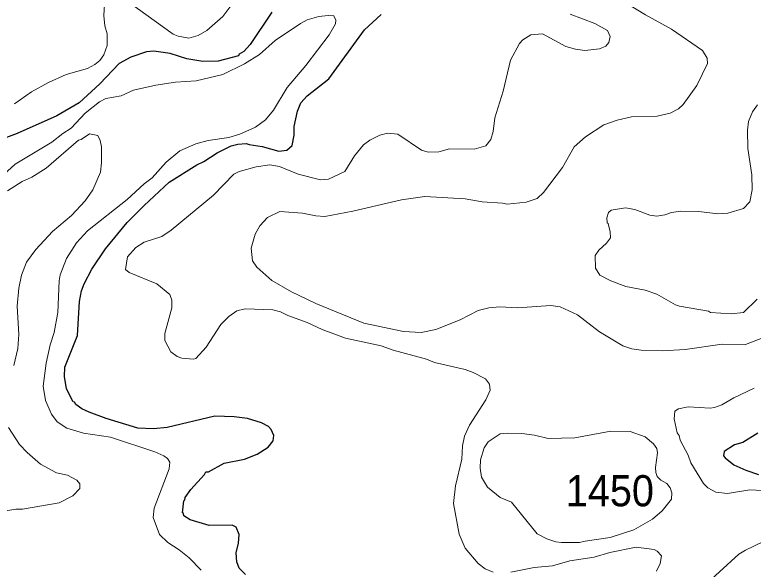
# Model space of a CAD drawing. Extents: x 598.3 to 623.2, y 6902.2 to 6930.1.
# Drawn here: x 611.225 to 613.12, y 6907.601 to 6909.024 of the extents above; entities that cross this region are included whole.
import ezdxf

# ---------------------------------------------------------------- set-up
doc = ezdxf.new("R2010")
doc.units = 0
doc.header["$LTSCALE"] = 0.032
doc.layers.add('1', color=7, linetype='Continuous', lineweight=25)
doc.layers.add('2', color=7, linetype='Continuous', lineweight=13)
doc.layers.add('21', color=7, linetype='Continuous')

msp = doc.modelspace()

# ---------------------------------------------------------------- linework, layer by layer
at = {"layer": '1'}
for points in [[(611.7929, 6907.7085), (611.783, 6907.7136), (611.7235, 6907.7128), (611.6749, 6907.7272), (611.6588, 6907.7377), (611.6577, 6907.7439), (611.6553, 6907.7456), (611.6585, 6907.7765), (611.6616, 6907.7787), (611.6621, 6907.7846), (611.6767, 6907.8057), (611.7115, 6907.8436), (611.7152, 6907.851), (611.722, 6907.8507), (611.7623, 6907.8732), (611.8141, 6907.8837), (611.8473, 6907.8957), (611.8748, 6907.914), (611.888, 6907.9301), (611.8898, 6907.9439), (611.8828, 6907.9594), (611.876, 6907.9671), (611.8584, 6907.9769), (611.8219, 6907.988), (611.7882, 6907.9921), (611.7382, 6907.9938), (611.616, 6907.9645), (611.5814, 6907.9614), (611.5412, 6907.963), (611.4597, 6907.9877), (611.4156, 6908.0036), (611.3975, 6908.0125), (611.3821, 6908.024), (611.3783, 6908.03), (611.3748, 6908.0307), (611.3581, 6908.0636), (611.3525, 6908.0954), (611.3538, 6908.1191), (611.3864, 6908.201), (611.3913, 6908.2883), (611.3964, 6908.3156), (611.4028, 6908.3336), (611.4231, 6908.3712), (611.4582, 6908.4233), (611.5138, 6908.491), (611.557, 6908.5349), (611.6214, 6908.5945), (611.6922, 6908.6387), (611.7105, 6908.6471), (611.744, 6908.6695), (611.7804, 6908.6873), (611.7977, 6908.6923), (611.819, 6908.6938), (611.8263, 6908.6908), (611.8601, 6908.686), (611.9022, 6908.6738), (611.9229, 6908.6766), (611.9369, 6908.6886), (611.9417, 6908.7155), (611.9418, 6908.7371), (611.9504, 6908.7766), (611.9594, 6908.798), (611.9755, 6908.8159), (612.0304, 6908.8596), (612.122, 6908.9851), (612.1649, 6909.0246)], [(611.8846, 6909.0308), (611.8294, 6908.9476), (611.8128, 6908.9301), (611.801, 6908.923), (611.7987, 6908.9187), (611.7472, 6908.9052), (611.7073, 6908.9043), (611.6668, 6908.9108), (611.6241, 6908.9247), (611.582, 6908.9311), (611.5629, 6908.9294), (611.5232, 6908.9152), (611.4931, 6908.8993)], [(611.4931, 6908.8993), (611.4437, 6908.8467), (611.39, 6908.7979), (611.3328, 6908.765), (611.2317, 6908.7193), (611.1319, 6908.6824)], [(613.1315, 6907.9499), (613.0931, 6907.9259), (613.0718, 6907.92), (613.0447, 6907.9033), (613.0435, 6907.892), (613.0471, 6907.8868), (613.0698, 6907.8688), (613.1002, 6907.8551), (613.1333, 6907.844)], [(611.8172, 6907.5874), (611.8011, 6907.6034), (611.7952, 6907.62), (611.7929, 6907.6424), (611.7992, 6907.668), (611.801, 6907.6903), (611.7929, 6907.7085)]]:
    msp.add_lwpolyline(points, dxfattribs=at)
at = {"layer": '2'}
for points in [[(611.7846, 6909.0539), (611.7591, 6909.0197), (611.7181, 6908.9836), (611.6952, 6908.9713), (611.672, 6908.9643), (611.6444, 6908.969), (611.6313, 6908.9746), (611.519, 6909.0558)], [(612.2168, 6908.549), (612.2774, 6908.5579), (612.3808, 6908.5514), (612.4241, 6908.5443), (612.476, 6908.5409), (612.4887, 6908.5378), (612.5366, 6908.5433), (612.5649, 6908.5523), (612.5819, 6908.5676), (612.63, 6908.6319), (612.6603, 6908.6855), (612.6892, 6908.7111), (612.7365, 6908.7415), (612.7701, 6908.7537), (612.8076, 6908.7619), (612.8727, 6908.7637), (612.9067, 6908.7716), (612.9275, 6908.7828), (612.9398, 6908.7942), (612.9748, 6908.8423), (613.0021, 6908.899), (613.0017, 6908.9128), (612.989, 6908.9328), (612.9102, 6908.9876), (612.8433, 6909.0238), (612.7912, 6909.0553)], [(611.4556, 6909.0503), (611.4537, 6909.0225), (611.4565, 6908.9957), (611.4625, 6908.9749), (611.4625, 6908.9457), (611.4534, 6908.9209), (611.4431, 6908.9068), (611.4302, 6908.8965), (611.4116, 6908.8861), (611.3567, 6908.8707), (611.3119, 6908.8501), (611.268, 6908.8265), (611.2248, 6908.7952)], [(612.0438, 6909.0215), (612.029, 6909.0225), (612.0049, 6909.0193), (611.9755, 6909.0111), (611.9577, 6909.0014), (611.8932, 6908.9578), (611.8527, 6908.9224), (611.8147, 6908.8984), (611.7591, 6908.8704), (611.6908, 6908.8547), (611.6377, 6908.851), (611.5867, 6908.8435), (611.5296, 6908.8305), (611.4984, 6908.8162), (611.4585, 6908.8088), (611.4421, 6908.8006), (611.406, 6908.7717), (611.37, 6908.7334), (611.3481, 6908.7194), (611.3199, 6908.697), (611.2258, 6908.6408), (611.1683, 6908.5883)], [(611.7036, 6907.5981), (611.6726, 6907.6303), (611.6469, 6907.6506), (611.6176, 6907.669), (611.5967, 6907.6899), (611.58, 6907.7339), (611.5828, 6907.7579), (611.621, 6907.8588), (611.6228, 6907.8755), (611.617, 6907.8846), (611.6077, 6907.892), (611.5848, 6907.9019), (611.4706, 6907.9394), (611.4014, 6907.95), (611.3584, 6907.9632), (611.334, 6907.979), (611.3198, 6907.9991), (611.3038, 6908.0342), (611.2983, 6908.0705), (611.3054, 6908.1295), (611.316, 6908.1766), (611.3265, 6908.2088), (611.3355, 6908.2595), (611.3387, 6908.3408), (611.3419, 6908.3563), (611.358, 6908.3982), (611.3831, 6908.4389), (611.412, 6908.4692), (611.5134, 6908.55), (611.5569, 6908.5902), (611.5779, 6908.6053), (611.6136, 6908.6457), (611.6485, 6908.6751), (611.6895, 6908.6932), (611.7216, 6908.7011), (611.7746, 6908.7093), (611.8028, 6908.7175), (611.8428, 6908.7359), (611.868, 6908.7547), (611.8886, 6908.7794), (611.9238, 6908.8373), (611.972, 6908.8943), (612.0318, 6908.9726), (612.0478, 6909.0008), (612.0485, 6909.0107), (612.0438, 6909.0215)], [(612.4321, 6907.6021), (612.4143, 6907.6158), (612.3806, 6907.6551), (612.3652, 6907.6907), (612.3506, 6907.7697), (612.356, 6907.8147), (612.3723, 6907.8836), (612.374, 6907.9176), (612.3789, 6907.9422), (612.3917, 6907.9708), (612.4338, 6908.0356), (612.4444, 6908.0602), (612.4429, 6908.0761), (612.4324, 6908.0898), (612.401, 6908.1061), (612.3808, 6908.1135), (612.3017, 6908.1315), (612.2815, 6908.1403), (612.1958, 6908.1632), (612.165, 6908.1743), (612.0733, 6908.1938), (612.0136, 6908.2161), (611.9755, 6908.2342), (611.9256, 6908.2519), (611.9067, 6908.2617), (611.887, 6908.2665), (611.8166, 6908.2689), (611.7946, 6908.264), (611.7741, 6908.2494), (611.7541, 6908.2288), (611.7161, 6908.1705), (611.6895, 6908.1421), (611.6834, 6908.1403), (611.6538, 6908.1422), (611.6417, 6908.1468), (611.6259, 6908.1592), (611.6103, 6908.1879), (611.6099, 6908.2061), (611.6284, 6908.272), (611.6277, 6908.2911), (611.6228, 6908.3061), (611.5894, 6908.3331), (611.519, 6908.3622), (611.5096, 6908.3703), (611.5145, 6908.4026), (611.5354, 6908.4267), (611.557, 6908.4407), (611.6028, 6908.4549), (611.6265, 6908.4709), (611.7349, 6908.5607), (611.7871, 6908.6146), (611.8009, 6908.6218), (611.8446, 6908.634), (611.8794, 6908.6388), (611.9039, 6908.6345), (611.9518, 6908.6152), (612.0092, 6908.6001), (612.0302, 6908.6019), (612.0722, 6908.622), (612.0969, 6908.6616), (612.1195, 6908.6903), (612.1358, 6908.7019), (612.1614, 6908.7147), (612.1813, 6908.7198), (612.2078, 6908.718), (612.2686, 6908.6763), (612.286, 6908.6711), (612.3126, 6908.6725), (612.34, 6908.6801), (612.4037, 6908.6794), (612.4338, 6908.6875), (612.4462, 6908.7042), (612.4523, 6908.7246), (612.4566, 6908.7598), (612.4777, 6908.8278), (612.4971, 6908.9074), (612.5202, 6908.95), (612.5286, 6908.9594), (612.5491, 6908.9723), (612.5785, 6908.9756), (612.6385, 6908.943), (612.6636, 6908.936), (612.6879, 6908.9328), (612.7248, 6908.9366), (612.741, 6908.9435), (612.7492, 6908.9532), (612.7528, 6908.968), (612.746, 6908.9839), (612.713, 6909.0021), (612.6497, 6909.0256)], [(613.1302, 6908.7927), (613.1174, 6908.7746), (613.1075, 6908.7501), (613.1049, 6908.7281), (613.1058, 6908.6809), (613.1155, 6908.6136), (613.1171, 6908.5744), (613.1106, 6908.5436), (613.0946, 6908.5265), (613.0546, 6908.5151), (613.0291, 6908.5127), (612.9801, 6908.519), (612.934, 6908.5198), (612.9102, 6908.5167), (612.8924, 6908.5102), (612.8718, 6908.507), (612.854, 6908.5095), (612.8158, 6908.524), (612.792, 6908.5287), (612.7551, 6908.5224), (612.7481, 6908.5162), (612.744, 6908.503), (612.7448, 6908.4902), (612.7474, 6908.4885), (612.7527, 6908.467), (612.7535, 6908.4516), (612.743, 6908.438), (612.7233, 6908.42), (612.7141, 6908.4062), (612.7149, 6908.374), (612.7259, 6908.3559), (612.7545, 6908.3409), (612.7931, 6908.3265), (612.8426, 6908.317), (612.8718, 6908.3073), (612.9203, 6908.2799), (612.9307, 6908.2763), (613.0051, 6908.2632), (613.0102, 6908.2594), (613.0633, 6908.2567), (613.0942, 6908.2601), (613.13, 6908.294)], [(611.2067, 6908.5718), (611.2441, 6908.5959), (611.2691, 6908.6069), (611.3061, 6908.6306), (611.3885, 6908.7022), (611.3952, 6908.7038), (611.4167, 6908.7182), (611.438, 6908.7141), (611.4446, 6908.7015), (611.4479, 6908.685), (611.4479, 6908.644), (611.4447, 6908.6203), (611.4251, 6908.5747), (611.4058, 6908.5465), (611.3708, 6908.509), (611.3218, 6908.468), (611.2791, 6908.4216), (611.2555, 6908.3889), (611.2421, 6908.3554), (611.2358, 6908.3221), (611.2311, 6908.2763), (611.2358, 6908.2031), (611.2327, 6908.1672), (611.223, 6908.1235)], [(613.1882, 6908.2121), (613.0994, 6908.1775), (613.0401, 6908.1789), (612.9449, 6908.1648), (612.8858, 6908.1613), (612.8316, 6908.1629), (612.8077, 6908.1662), (612.7852, 6908.1742), (612.7248, 6908.2102), (612.6691, 6908.254), (612.6246, 6908.2747), (612.6002, 6908.2778), (612.5149, 6908.2722), (612.4691, 6908.2747), (612.4415, 6908.2715), (612.4139, 6908.2646), (612.3678, 6908.2408), (612.3057, 6908.2163), (612.2679, 6908.2083), (612.2221, 6908.2114), (612.1208, 6908.2327), (611.9972, 6908.2833), (611.9352, 6908.3127), (611.8846, 6908.3419), (611.8457, 6908.3764), (611.835, 6908.3928), (611.8317, 6908.4246), (611.8416, 6908.4606), (611.8542, 6908.4824), (611.8733, 6908.5033), (611.9048, 6908.5189), (611.9634, 6908.515), (611.9971, 6908.5077), (612.0203, 6908.5062), (612.0926, 6908.5199), (612.2168, 6908.549)], [(613.1218, 6908.0656), (613.07, 6908.0405)], [(613.07, 6908.0405), (613.0392, 6908.0227), (613.0203, 6908.0156), (613.0094, 6908.014), (612.9523, 6908.018), (612.928, 6908.0124), (612.9181, 6908.0064), (612.9164, 6907.987), (612.9243, 6907.9513), (612.9299, 6907.9441), (612.9321, 6907.9322), (612.9526, 6907.8939), (612.9594, 6907.8737), (612.9915, 6907.8208), (613.0027, 6907.8094), (613.0235, 6907.7986), (613.0532, 6907.7954), (613.1104, 6907.8043), (613.159, 6907.8019)], [(611.2094, 6907.9643), (611.2375, 6907.9207), (611.2566, 6907.9002), (611.2914, 6907.8703), (611.332, 6907.8486), (611.3606, 6907.8423), (611.384, 6907.8294), (611.3921, 6907.8203), (611.3921, 6907.8078), (611.3737, 6907.7891), (611.3391, 6907.7716), (611.2446, 6907.755), (611.2276, 6907.7549), (611.1582, 6907.7435)], [(613.6225, 6907.5953), (613.5989, 6907.6056), (613.5574, 6907.6191), (613.4849, 6907.6536), (613.4423, 6907.6911), (613.4064, 6907.7151), (613.3956, 6907.7192), (613.3547, 6907.725), (613.2806, 6907.7233), (613.2518, 6907.7185), (613.2138, 6907.7045), (613.0998, 6907.6499), (613.0829, 6907.639), (612.9735, 6907.5393)], [(612.8714, 6907.5957), (612.881, 6907.6158), (612.884, 6907.6349), (612.8731, 6907.6468), (612.8654, 6907.6512), (612.8193, 6907.6577), (612.7515, 6907.6433), (612.7115, 6907.6316), (612.649, 6907.6221), (612.6046, 6907.6098), (612.5573, 6907.6052), (612.4976, 6907.5931)], [(612.452, 6907.593), (612.4321, 6907.6021)]]:
    msp.add_lwpolyline(points, dxfattribs=at)
msp.add_lwpolyline([(612.7543, 6907.9548), (612.8036, 6907.954), (612.8427, 6907.941), (612.8633, 6907.9228), (612.8718, 6907.9111), (612.8742, 6907.8993), (612.8687, 6907.8618), (612.8695, 6907.8494), (612.8732, 6907.8386), (612.8828, 6907.8292), (612.8976, 6907.8205), (612.906, 6907.8097), (612.9107, 6907.7968), (612.9098, 6907.7803), (612.8858, 6907.751), (612.8612, 6907.7295), (612.8131, 6907.7022), (612.7523, 6907.6821), (612.6887, 6907.6732), (612.6741, 6907.6692), (612.6277, 6907.6692), (612.613, 6907.6712), (612.5898, 6907.6787), (612.5656, 6907.6913), (612.4997, 6907.7731), (612.4706, 6907.7851), (612.4381, 6907.8116), (612.4225, 6907.8371), (612.4194, 6907.86), (612.4197, 6907.8816), (612.4297, 6907.9125), (612.4396, 6907.9281), (612.4704, 6907.9482), (612.4895, 6907.9501), (612.526, 6907.9492), (612.5581, 6907.9452), (612.5937, 6907.9363), (612.6615, 6907.9379)], close=True, dxfattribs=at)

# ---------------------------------------------------------------- texts
at = {"layer": '21', "width": 0.95}
msp.add_text('1450', height=0.08, dxfattribs=at).set_placement((612.6387, 6907.7623))

doc.saveas('drawing.dxf')
